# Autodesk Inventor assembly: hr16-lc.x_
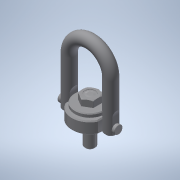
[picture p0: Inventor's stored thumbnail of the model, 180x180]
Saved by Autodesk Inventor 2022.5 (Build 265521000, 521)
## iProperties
Part Number: hr16-lc.x_
Material: 一般
Document SubType Name: Assembly
Designer: ImaoCorp
Sending System: SOLIDWORKS 2017-2017317
MC: AMD64
MC_MODEL: Intel64 Family 6 Model 60 Stepping 3, GenuineIntel
OS: Windows_NT
FRU: Parasolid Version 29.0, build 201,  4-17-2017
FORMAT: text
GUISE: transmit
KEY: hr16-lc
FILE: hr16-lc.x_t
DATE: Mon Jul 01 17:37:30 2019
Author: ImaoCorp
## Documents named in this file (3)
- X:\14_SW2022-Inv2022\00_全2023-1023新製品(TCC)まで\h\hr16-lc\HR16-LC.iam
- X:\14_SW2022-Inv2022\00_全2023-1023新製品(TCC)まで\h\hr16-lc\hr16-lc_01.ipt
- X:\14_SW2022-Inv2022\00_全2023-1023新製品(TCC)まで\h\hr16-lc\hr16-lc_02.ipt
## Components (2 placed, 2 different names)
1. hr16-lc_01
2. hr16-lc_02
